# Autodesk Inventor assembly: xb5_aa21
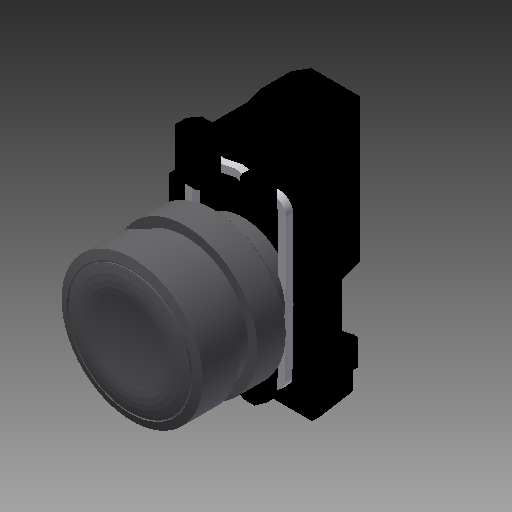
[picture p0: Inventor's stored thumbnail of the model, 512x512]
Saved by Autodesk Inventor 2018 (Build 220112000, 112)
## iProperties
Company: TraceParts S.A.
Created: 2018-05
Part Number: xb5_aa21
Checked By: TraceParts S.A.
Catalog Web Link: www.traceparts.com
Document SubType Name: Assembly
Designer: TraceParts
REFERENCE: XB5 AA21
DESIGN: Unité de commande et de signalisation Ø 22 Harmony XB5 plastique - Boutons-poussoirs à impulsion sans marquage à poussoir affleurant - Produit complet, XB5 AA21
SUPPLIER: Schneider Electric
TraceParts.PartNumber: 10-29052009-073937
TraceParts.PartTitle: Unité de commande et de signalisation Ø 22 Harmony XB5 plastique - Boutons-poussoirs à impulsion sans marquage à poussoir affleurant - Produit complet
TraceParts.InstanceId: 10-29052009-073937E5626Q18BEFSN4HUPGCW8VOWH
TraceParts.PartStatus: Published
TraceParts.PartVersion: 1.1.5
TRACEPARTS: TRACEPARTS
TraceParts.PartLanguage: fr
TraceParts.ClassPath: SCHNEIDER_ELECTRIC:/F_SCHNEIDER/F_TELEMECANIQUE/F_TELEMECANIQUE.04/F_TELEMECANIQUE.04.010/10-29052009-073937
Author: TraceParts
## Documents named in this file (8)
- D:\01 Paralaia\Grupos de Traballo\GT Maquetas\CAD 3D\Botoneras Schneider\Pulsador XB5AA21\xb5_aa21.iam
- D:\01 Paralaia\Grupos de Traballo\GT Maquetas\CAD 3D\Botoneras Schneider\Pulsador XB5AA21\xb5_aa21_01.ipt
- D:\01 Paralaia\Grupos de Traballo\GT Maquetas\CAD 3D\Botoneras Schneider\Pulsador XB5AA21\xb5_aa21_02.ipt
- D:\01 Paralaia\Grupos de Traballo\GT Maquetas\CAD 3D\Botoneras Schneider\Pulsador XB5AA21\xb5_aa21_03.ipt
- D:\01 Paralaia\Grupos de Traballo\GT Maquetas\CAD 3D\Botoneras Schneider\Pulsador XB5AA21\xb5_aa21_04.ipt
- D:\01 Paralaia\Grupos de Traballo\GT Maquetas\CAD 3D\Botoneras Schneider\Pulsador XB5AA21\xb5_aa21_05.ipt
- D:\01 Paralaia\Grupos de Traballo\GT Maquetas\CAD 3D\Botoneras Schneider\Pulsador XB5AA21\xb5_aa21_06.ipt
- D:\01 Paralaia\Grupos de Traballo\GT Maquetas\CAD 3D\Botoneras Schneider\Pulsador XB5AA21\xb5_aa21_07.ipt
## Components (7 placed, 7 different names)
1. xb5_aa21_01:1
2. xb5_aa21_02:1
3. xb5_aa21_03:1
4. xb5_aa21_04:1
5. xb5_aa21_05:1
6. xb5_aa21_06:1
7. xb5_aa21_07:1
